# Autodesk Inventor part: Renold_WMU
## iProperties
Author: Administrator
Shininess: 33.0
Angle Display Precision: 2
Document Length Units: 11272
Document Angle Units: 11286
Document Time Units: 11279
Document Mass Units: 11290
Document Length Units Precision: 3
Document Angle Units Precision: 2
Compacted: True
PropertySet Name: _Private Model Information
Created: 2002-04
Part Number: Renold_WMU
Material: ASTM A36 HRS
Document SubType Name: Modeling
Designer: Administrator
Control State: 0
Master: False
Checked Out: False
PropertySet Name: Design Tracking Control
Density: 0.0
Volumn: 0.0
Area: 0.0
PropertySet Name: Model Information
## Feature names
1. body_from_top [Extrusion]
2. bolt_down_holes [Hole]
3. Fillet1
4. cutout_from_center [Extrusion]
5. Fillet2
6. input_pad [Extrusion]
7. top_bottom_cutout [Extrusion]
8. output_pad [Extrusion]
9. Chamfer1
10. shield_bolt_holes [Extrusion]
11. long_rib [Extrusion]
12. Rectangular Pattern1
13. short_rib [Extrusion]
14. Rectangular Pattern2
15. Hole2
16. oil_boss [Extrusion]
17. pipe_plug [Extrusion]
18. hex_in [Extrusion]
19. side_fill [Extrusion]
20. side_fill_plug [Extrusion]
21. side_fill_hex [Extrusion]
22. Mirror3
23. top_fill [Extrusion]
24. top_fill_plug [Extrusion]
25. top_fill_plug_hex [Extrusion]
26. bottom_fill [Extrusion]
27. bottom_filll_plug [Extrusion]
28. bottom_fill_plug_hex [Extrusion]
29. mirror_ouputpad_ribs
30. input_shaft [Revolution]
31. Revolution6
32. input_keyway [Extrusion]
33. end_of_input_chamf [Chamfer]
34. mirrored_inputshaft
35. Mirror4
36. output_shaft [Revolution]
37. Revolution5
38. keyway_on_output_shaft [Extrusion]
39. output_shaft_hole [Revolution]
40. shaft_hole_keyway [Extrusion]
